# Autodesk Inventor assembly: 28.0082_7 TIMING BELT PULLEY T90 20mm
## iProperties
Created: 2007-04
Part Number: 28.0082_7 TIMING BELT PULLEY T90 20mm
Document SubType Name: Assembly
Designer: Andy Moles
Author: Andy Moles
